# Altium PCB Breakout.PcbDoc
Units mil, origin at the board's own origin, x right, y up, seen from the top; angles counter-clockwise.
Board outline 280 x 700 mil, 2 copper layers (Top Layer, Bottom Layer); 0 components, 0 nets, 20 pads, 0 vias.
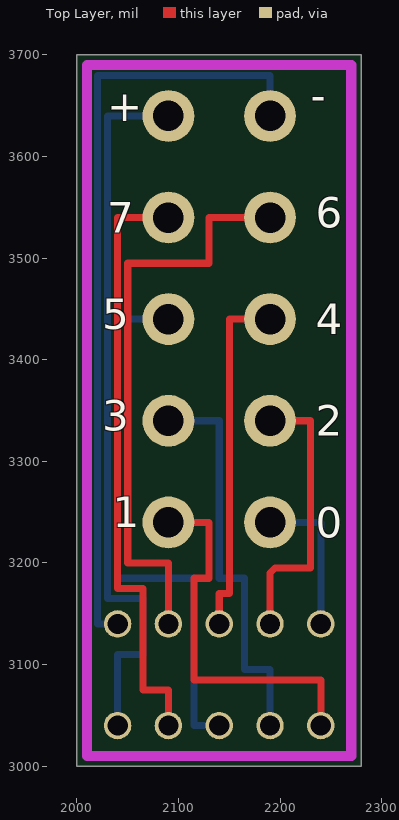
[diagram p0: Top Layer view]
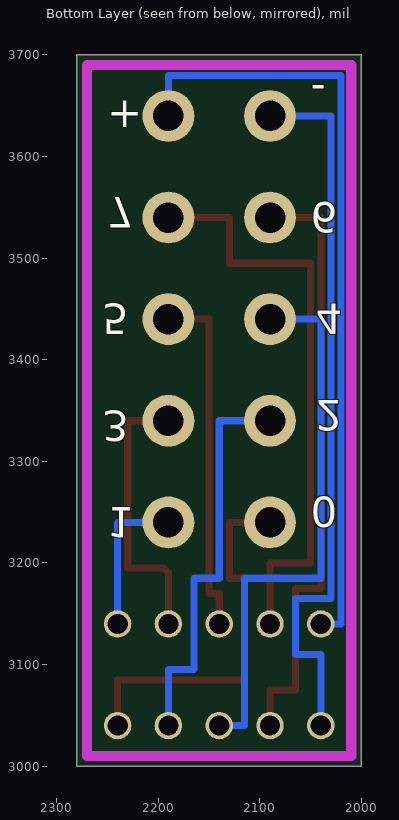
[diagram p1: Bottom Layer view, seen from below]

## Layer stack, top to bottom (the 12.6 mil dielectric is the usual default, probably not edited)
Top Layer: signal copper 1.4
Dielectric: dielectric 12.6, FR-4, Dk 4.8
Bottom Layer: signal copper 1.4

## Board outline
2000,3000 2280,3000 2280,3700 2000,3700

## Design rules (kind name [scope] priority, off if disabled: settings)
Clearance [All] p1: gap=7
ComponentClearance [All] p1: gap=10 collisioncheckmode=0
HoleSize [All] p1: absolutevalues=TRUE maxlimit=100 minlimit=15 maxpercent=80.000 minpercent=20.000
PolygonConnect [All] p1: connectstyle=Relief reliefconductorwidth=10 reliefentries=4 polygonreliefangle="90 Angle"
RoutingLayers [All] p1: top layer=Horizontal bottom layer=Vertical
RoutingVias [All] p1: holewidth=20 width=15 viastyle="Through Hole" minholewidth=28 minwidth=50 maxholewidth=28 maxwidth=50
SolderMaskExpansion [All] p1: expansion=4
TestPointUsage [All] p1: valid=0 allowmultiple=FALSE
Testpoint [All] p1: side=15 testpointundercomponent=TRUE minsize=40 maxsize=100 preferedsize=60 minholesize=0 maxholesize=40 preferedholesize=32 testpointgrid=1 style=1023 order=-539222988
Width [All] p1: maxlimit=7 minlimit=7 preferedwidth=7
15 further rules are at their usual default settings.

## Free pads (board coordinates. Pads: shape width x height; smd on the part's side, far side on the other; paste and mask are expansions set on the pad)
  round 27 hole 20: 1(2040,3040) 2(2040,3140) 3(2090,3040) 4(2090,3140) 5(2140,3040) 6(2140,3140) 7(2190,3040) 8(2190,3140) 9(2240,3040) 10(2240,3140)
  round 51 hole 30: 1(2090,3640) 2(2190,3640) 3(2090,3540) 4(2190,3540) 5(2090,3440) 6(2190,3440) 7(2090,3340) 8(2190,3340) 9(2090,3240) 10(2190,3240)

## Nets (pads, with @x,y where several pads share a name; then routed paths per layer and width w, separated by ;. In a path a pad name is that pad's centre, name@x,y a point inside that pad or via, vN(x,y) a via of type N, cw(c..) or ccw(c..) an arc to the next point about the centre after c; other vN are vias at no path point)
copper on no net: | length 4777.1
  Top Layer w7: 2090,3040 2090,3075 2065,3075 2065,3175 2040,3175 2040,3540 2090,3540 ; 2090,3140 2090,3200 2050,3200 2050,3495 2130,3495 2130,3540 2190,3540 ; 2090,3240 2130,3240 2130,3185 2115,3185 2115,3085 2240,3085 2240,3040 ; 2140,3140 2140,3170 2150,3170 2150,3440 2190,3440 ; 2190,3140 2190,3190 2195,3195 2230,3195 2230,3340 2190,3340
  Bottom Layer w7: 2040,3040 2040,3110 2065,3110 2065,3120 2065,3165 2030,3165 2030,3640 2090,3640 ; 2040,3140 2020,3140 2020,3680 2190,3680 2190,3640 ; 2090,3340 2140,3340 2140,3185 2165,3185 2165,3095 2190,3095 2190,3040 ; 2090,3440 2040,3440 2040,3185 2115,3185 2115,3040 2140,3040 ; 2190,3240 2240,3240 2240,3140

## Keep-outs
Keep-Out Layer:
  lines w10: 2010,3010 2270,3010 2270,3690 2010,3690 2010,3010

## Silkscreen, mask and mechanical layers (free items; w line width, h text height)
Top Overlay:
  text "-" at 2230,3645 h30
  text "+" at 2030,3635 h30
  text "6" at 2235,3530 h30
  text "7" at 2030,3525 h30
  text "5" at 2025,3430 h30
  text "4" at 2235,3425 h30
  text "3" at 2025,3330 h30
  text "2" at 2235,3325 h30
  text "1" at 2035,3235 h30
  text "0" at 2235,3225 h30
Bottom Overlay:
  text "-" at 2050,3680 h30 r180
  text "+" at 2250,3655 h30 r180
  text "7" at 2250,3560 h30 r180
  text "6" at 2050,3555 h30 r180
  text "4" at 2045,3455 h30 r180
  text "5" at 2255,3455 h30 r180
  text "2" at 2045,3360 h30 r180
  text "3" at 2255,3350 h30 r180
  text "0" at 2050,3265 h30 r180
  text "1" at 2250,3255 h30 r180
Drill Drawing:
  text ".LEGEND" at 2480,3200 h60
  text "Drill Drawing." at 2480,3100 h60

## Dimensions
2010,3010 to 2270,3010 on Mechanical 1
2010,3010 to 2010,3690 on Mechanical 1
